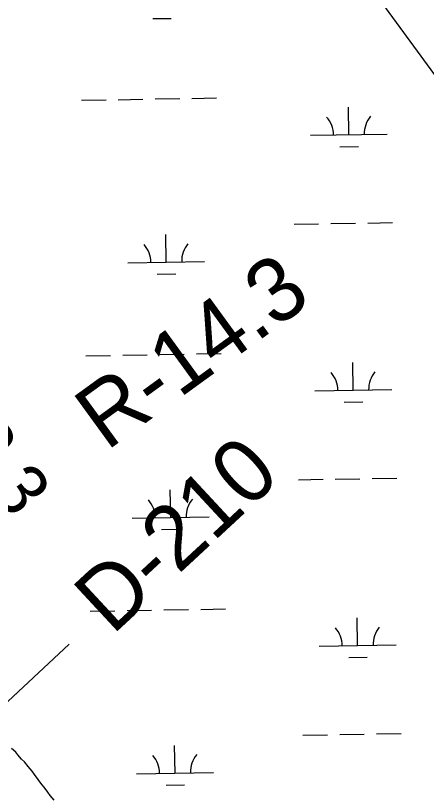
# Model space of a CAD drawing. Extents: x 3887375 to 3925618, y 296674 to 322633.
# Drawn here: x 3903987 to 3904521, y 304360 to 305377 of the extents above; entities that cross this region are included whole.
import ezdxf

# ---------------------------------------------------------------- set-up
doc = ezdxf.new("R2010")
doc.units = 0
for name, color, linetype in [('V-RIVR-RANG', 7, 'Continuous'), ('V-RIVR-RANG-IDEN', 7, 'Continuous'), ('V-UTIL-LINE', 7, 'Continuous'), ('V-WETL-SWMP', 7, 'Continuous')]:
    doc.layers.add(name, color=color, linetype=linetype)

msp = doc.modelspace()

# ---------------------------------------------------------------- linework, layer by layer
at = {"layer": 'V-RIVR-RANG'}
msp.add_line((3904056.2, 304558.7), (3903544.1, 304081.5), dxfattribs=at)
at = {"layer": 'V-UTIL-LINE'}
msp.add_lwpolyline([(3891385.6, 317757.3), (3896110, 314731.3), (3903763.5, 306349.6), (3906680.6, 302364)], dxfattribs=at)
at = {"layer": 'V-WETL-SWMP'}
for p, q in [((3904165.3, 305373.1), (3904189.3, 305373.5)), ((3904072.3, 305266.8), (3904104.3, 305267.4)), ((3904120.3, 305267.6), (3904152.3, 305268.2)), ((3904168.3, 305268.5), (3904200.2, 305269)), ((3904216.2, 305269.3), (3904248.2, 305269.8)), ((3904420.4, 305222), (3904419.8, 305258)), ((3904370.4, 305221.2), (3904470.4, 305222.9)), ((3904408.7, 305206.4), (3904432.7, 305206.8)), ((3904349, 305105.4), (3904381, 305105.9)), ((3904397, 305106.2), (3904429, 305106.7)), ((3904445, 305107), (3904477, 305107.6)), ((3904182.7, 305056.1), (3904182.1, 305092.1)), ((3904132.8, 305055.2), (3904232.7, 305056.9)), ((3904171, 305040.4), (3904195, 305040.9)), ((3904078, 304934.2), (3904110, 304934.7)), ((3904126, 304935), (3904158, 304935.6)), ((3904174, 304935.8), (3904206, 304936.4)), ((3904222, 304936.7), (3904254, 304937.2)), ((3904426.1, 304889.4), (3904425.5, 304925.4)), ((3904376.1, 304888.6), (3904476.1, 304890.3)), ((3904414.4, 304873.8), (3904438.4, 304874.2)), ((3904354.7, 304772.7), (3904386.7, 304773.3)), ((3904402.7, 304773.6), (3904434.7, 304774.1)), ((3904450.7, 304774.4), (3904482.7, 304774.9)), ((3904188.5, 304723.5), (3904187.8, 304759.5)), ((3904138.5, 304722.6), (3904238.4, 304724.3)), ((3904176.7, 304707.8), (3904200.7, 304708.2)), ((3904227.7, 304604), (3904259.7, 304604.6)), ((3904083.7, 304601.6), (3904115.7, 304602.1)), ((3904131.7, 304602.4), (3904163.7, 304602.9)), ((3904179.7, 304603.2), (3904211.7, 304603.8)), ((3904431.8, 304556.8), (3904431.2, 304592.8)), ((3904381.8, 304555.9), (3904481.8, 304557.7)), ((3904420.1, 304541.2), (3904444.1, 304541.6)), ((3904456.4, 304441.8), (3904488.4, 304442.3)), ((3904360.4, 304440.1), (3904392.4, 304440.7)), ((3904408.4, 304440.9), (3904440.4, 304441.5)), ((3903986.8, 304418), (3903981.5, 304422.8)), ((3904194.2, 304390.8), (3904193.5, 304426.8)), ((3903989.5, 304414.5), (3903986.8, 304418)), ((3903994.4, 304408.9), (3903989.5, 304414.5)), ((3903998.3, 304405.4), (3903994.4, 304408.9)), ((3904002.8, 304399.3), (3903998.3, 304405.4)), ((3904008.1, 304393.3), (3904002.8, 304399.3)), ((3904011.2, 304388.9), (3904008.1, 304393.3)), ((3904144.2, 304390), (3904244.2, 304391.7)), ((3904016.1, 304382.4), (3904011.2, 304388.9)), ((3904019.7, 304377.6), (3904016.1, 304382.4)), ((3904025, 304370.7), (3904019.7, 304377.6)), ((3904028.6, 304365.9), (3904025, 304370.7)), ((3904182.4, 304375.2), (3904206.4, 304375.6)), ((3904031.7, 304361.6), (3904028.6, 304365.9)), ((3904037, 304355.5), (3904031.7, 304361.6))]:
    msp.add_line(p, q, dxfattribs=at)
for centre, start, end in [((3904365.2, 305221.6), 0.2115, 41.7552), ((3904475.6, 305223.5), 140.2115, 181.7552), ((3904127.5, 305055.6), 0.2115, 41.7552), ((3904238, 305057.5), 140.2115, 181.7552), ((3904370.9, 304888.9), 0.2115, 41.7552), ((3904481.3, 304890.8), 140.2115, 181.7552), ((3904243.7, 304724.9), 140.2115, 181.7552), ((3904133.2, 304723), 0.2115, 41.7552), ((3904376.6, 304556.3), 0.2115, 41.7552), ((3904487, 304558.2), 140.2115, 181.7552), ((3904138.9, 304390.4), 0.2115, 41.7552), ((3904249.4, 304392.3), 140.2115, 181.7552)]:
    msp.add_arc(centre, 35.2, start, end, dxfattribs=at)

# ---------------------------------------------------------------- texts
at = {"layer": 'V-RIVR-RANG'}
msp.add_text('2.3', height=67, rotation=305.8583, dxfattribs=at).set_placement((3903908.9, 304821.4))
at = {"layer": 'V-RIVR-RANG-IDEN'}
for s, rotation, p in [('R-14.3', 35.9984, (3904104.9, 304809.4)), ('D-210', 42.8373, (3904112.4, 304569.4))]:
    msp.add_text(s, height=83, rotation=rotation, dxfattribs=at).set_placement(p)

doc.saveas('drawing.dxf')
